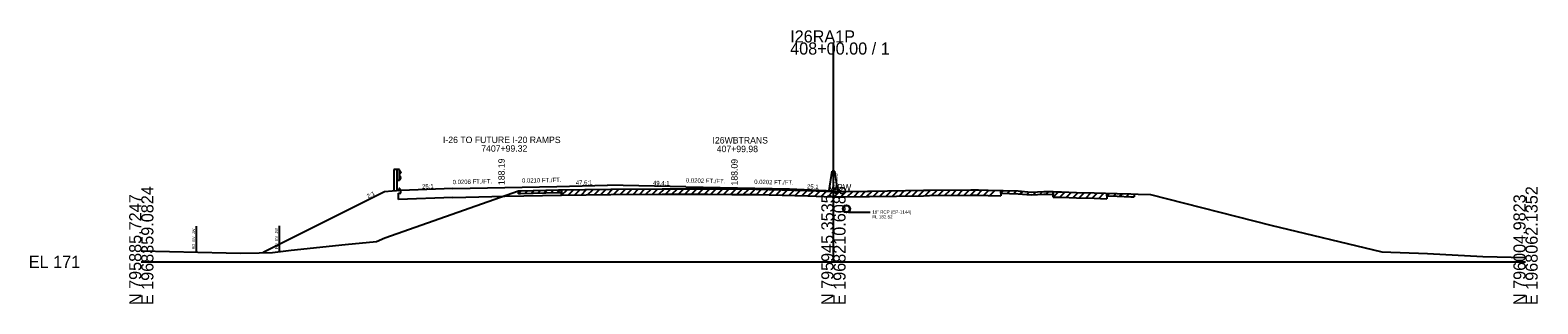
# Model space of a CAD drawing. Extents: x -44 to 4323, y -10 to 9601.
# Drawn here: x -25.7 to 322.8, y 5490.3 to 5553.5 of the extents above; entities that cross this region are included whole.
import ezdxf

# ---------------------------------------------------------------- set-up
doc = ezdxf.new("R2010")
doc.units = 0
for name, color, linetype in [('1', 7, 'Continuous'), ('DateStamp', 7, 'Continuous'), ('NotForConst', 7, 'Continuous'), ('QCQA', 7, 'Continuous'), ('RD_SHT_Bndy', 7, 'Continuous'), ('RD_SHT_Iplotshp', 7, 'Continuous'), ('RD_SHT_TX', 7, 'Continuous'), ('RD_Sketch2', 7, 'Continuous'), ('RD_XS_Base', 7, 'Continuous'), ('RD_XS_ExGround', 7, 'Continuous'), ('RD_XS_Misc_Line', 7, 'Continuous'), ('RD_XS_Pave', 7, 'Continuous'), ('RD_XS_PaveShd', 7, 'Continuous'), ('RD_XS_Pipe', 7, 'Continuous'), ('RD_XS_TX_Elev_PR', 7, 'Continuous'), ('RD_XS_TX_MatchLine', 7, 'Continuous'), ('RD_XS_TX_Profile', 7, 'Continuous'), ('RD_XS_TX_ShdSlope', 7, 'Continuous'), ('RD_XS_TX_Slope', 7, 'Continuous'), ('seal', 7, 'Continuous'), ('TR SN EXTRUDED PANEL SIGNS - GROUND MOUNTED', 7, 'Continuous')]:
    doc.layers.add(name, color=color, linetype=linetype)

msp = doc.modelspace()

# ---------------------------------------------------------------- linework, layer by layer
at = {"layer": 'DateStamp'}
msp.add_lwpolyline([(0, 5502.57), (19.61, 5502.07), (22.94, 5502.01), (27.25, 5502.11), (30.35, 5502.2), (34.65, 5502.67), (47.14, 5503.99), (54.38, 5504.74), (56.32, 5505.52), (87.16, 5516.38), (87.63, 5516.39), (96.47, 5516.63), (108.53, 5516.78), (120.44, 5516.89), (130.97, 5516.89), (136.53, 5516.84), (142.15, 5516.8), (154.06, 5516.49), (159.79, 5516.26), (162.44, 5516.24), (167.91, 5516.33), (168.35, 5516.34), (180.8, 5516.54), (182.21, 5516.56), (191.78, 5516.64), (192.21, 5516.64), (193.5, 5516.65), (195.74, 5516.59), (202.68, 5516.38), (205.73, 5516.09), (208.63, 5516.26), (209.51, 5516.24), (210.82, 5516.23), (211.42, 5516.21), (212.69, 5516.17), (216.18, 5516.05), (220.27, 5515.93), (225.56, 5515.78), (228.76, 5515.68), (230.43, 5515.65), (233.26, 5515.58), (261.12, 5508.48), (286.76, 5502.32), (297.34, 5501.9), (310.13, 5501.21), (320, 5501.04)], dxfattribs=at)
at = {"layer": 'NotForConst'}
for p, q in [((87.16, 5515.75), (87.8, 5516.4)), ((88.66, 5515.8), (89.3, 5516.44)), ((90.16, 5515.83), (90.8, 5516.48)), ((91.66, 5515.87), (92.3, 5516.52)), ((93.16, 5515.91), (93.8, 5516.56)), ((94.66, 5515.95), (95.3, 5516.6)), ((96.16, 5515.99), (96.8, 5516.63)), ((97.16, 5515.39), (98.43, 5516.65)), ((98.66, 5515.4), (99.93, 5516.67)), ((100.16, 5515.42), (101.43, 5516.69)), ((101.66, 5515.44), (102.93, 5516.71)), ((103.16, 5515.46), (104.43, 5516.73)), ((104.66, 5515.48), (105.93, 5516.75)), ((106.16, 5515.5), (107.43, 5516.77)), ((107.66, 5515.52), (108.93, 5516.79)), ((109.17, 5515.54), (110.43, 5516.8)), ((110.67, 5515.55), (111.93, 5516.81)), ((112.17, 5515.57), (113.43, 5516.83)), ((113.67, 5515.58), (114.93, 5516.84)), ((115.17, 5515.59), (116.43, 5516.86)), ((116.67, 5515.61), (117.93, 5516.87)), ((118.17, 5515.62), (119.43, 5516.88)), ((119.67, 5515.64), (120.93, 5516.89)), ((121.17, 5515.64), (122.42, 5516.89)), ((122.67, 5515.64), (123.92, 5516.89)), ((124.17, 5515.64), (125.42, 5516.89)), ((125.67, 5515.64), (126.92, 5516.89)), ((127.17, 5515.64), (128.42, 5516.89)), ((128.67, 5515.64), (129.92, 5516.89)), ((130.17, 5515.64), (131.42, 5516.88)), ((131.67, 5515.63), (132.91, 5516.87)), ((133.17, 5515.62), (134.41, 5516.86)), ((134.67, 5515.61), (135.91, 5516.85)), ((136.17, 5515.59), (137.41, 5516.83)), ((137.67, 5515.58), (138.91, 5516.82)), ((139.17, 5515.57), (140.41, 5516.81)), ((140.67, 5515.56), (141.92, 5516.8)), ((142.18, 5515.55), (143.39, 5516.76)), ((143.68, 5515.51), (144.89, 5516.72)), ((145.18, 5515.47), (146.39, 5516.69)), ((146.68, 5515.43), (147.9, 5516.65)), ((148.18, 5515.39), (149.4, 5516.61)), ((149.68, 5515.35), (150.9, 5516.57)), ((151.18, 5515.31), (152.4, 5516.53)), ((152.68, 5515.27), (153.9, 5516.49)), ((154.18, 5515.23), (155.38, 5516.43)), ((155.68, 5515.17), (156.88, 5516.37)), ((157.18, 5515.11), (158.38, 5516.31)), ((158.68, 5515.05), (159.89, 5516.26)), ((160.18, 5515), (161.42, 5516.25)), ((161.68, 5515), (162.94, 5516.25)), ((163.18, 5515), (164.45, 5516.27)), ((164.68, 5515.03), (165.95, 5516.3)), ((166.18, 5515.05), (167.45, 5516.32)), ((167.68, 5515.08), (168.95, 5516.35)), ((169.18, 5515.1), (170.45, 5516.37)), ((170.68, 5515.13), (171.96, 5516.4)), ((172.18, 5515.15), (173.46, 5516.42)), ((173.68, 5515.18), (174.96, 5516.45)), ((175.19, 5515.2), (176.46, 5516.47)), ((176.69, 5515.23), (177.96, 5516.5)), ((178.19, 5515.25), (179.46, 5516.52)), ((179.69, 5515.28), (180.96, 5516.55)), ((181.19, 5515.3), (182.45, 5516.56)), ((182.69, 5515.31), (183.95, 5516.57)), ((184.19, 5515.33), (185.45, 5516.59)), ((185.69, 5515.34), (186.95, 5516.6)), ((187.19, 5515.35), (188.45, 5516.61)), ((188.69, 5515.37), (189.95, 5516.63)), ((190.19, 5515.38), (191.45, 5516.64)), ((191.69, 5515.39), (192.94, 5516.65)), ((193.19, 5515.4), (194.42, 5516.62)), ((194.69, 5515.37), (195.91, 5516.58)), ((196.19, 5515.33), (197.41, 5516.54)), ((198.68, 5515.87), (199.28, 5516.48)), ((200.18, 5515.83), (200.78, 5516.44)), ((201.68, 5515.78), (202.28, 5516.39)), ((203.18, 5515.71), (203.75, 5516.28)), ((204.68, 5515.57), (205.25, 5516.14)), ((206.18, 5515.49), (206.84, 5516.16)), ((207.68, 5515.58), (208.34, 5516.24)), ((209.18, 5515.62), (209.8, 5516.23)), ((210.82, 5514.98), (212.04, 5516.19)), ((212.32, 5514.93), (213.53, 5516.14)), ((213.82, 5514.88), (215.03, 5516.09)), ((215.32, 5514.83), (216.54, 5516.04)), ((216.82, 5514.78), (218.04, 5515.99)), ((218.33, 5514.74), (219.54, 5515.95)), ((219.83, 5514.69), (221.04, 5515.91)), ((221.33, 5514.65), (222.54, 5515.86)), ((223.22, 5515.22), (223.83, 5515.83)), ((224.72, 5515.18), (225.33, 5515.79)), ((226.22, 5515.14), (226.82, 5515.74)), ((227.72, 5515.09), (228.32, 5515.69))]:
    msp.add_line(p, q, dxfattribs=at)
at = {"layer": 'QCQA'}
for p, q in [((97.16, 5516.64), (108.53, 5516.78)), ((97.16, 5516.64), (97.16, 5515.43)), ((108.53, 5516.78), (120.44, 5516.89)), ((120.44, 5516.89), (130.97, 5516.89)), ((130.97, 5516.89), (136.53, 5516.84)), ((136.53, 5516.84), (142.15, 5516.8)), ((142.15, 5516.8), (154.06, 5516.49)), ((154.06, 5516.49), (159.79, 5516.26)), ((159.79, 5516.26), (160, 5516.25))]:
    msp.add_line(p, q, dxfattribs=at)
at = {"layer": 'RD_SHT_Bndy'}
for p, q in [((160, 5500), (160, 5550.68)), ((0, 5500), (160, 5500)), ((160, 5500), (320, 5500))]:
    msp.add_line(p, q, dxfattribs=at)
at = {"layer": 'RD_SHT_Iplotshp'}
for p, q in [((87.16, 5515.75), (87.16, 5516.38)), ((87.16, 5515.75), (87.63, 5515.77)), ((87.63, 5515.77), (96.47, 5516)), ((96.47, 5516), (97.16, 5516.01)), ((97.16, 5515.39), (97.16, 5516.64)), ((97.16, 5516.64), (97.16, 5516.01)), ((97.16, 5515.39), (108.53, 5515.53)), ((108.53, 5515.53), (120.44, 5515.64)), ((120.44, 5515.64), (130.97, 5515.64)), ((130.97, 5515.64), (136.53, 5515.59)), ((136.53, 5515.59), (142.15, 5515.55)), ((142.15, 5515.55), (154.06, 5515.24)), ((154.06, 5515.24), (159.79, 5515.01)), ((159.79, 5515.01), (162.44, 5514.99)), ((162.44, 5514.99), (167.91, 5515.08)), ((167.91, 5515.08), (168.35, 5515.09)), ((168.35, 5515.09), (180.8, 5515.29)), ((180.8, 5515.29), (182.21, 5515.31)), ((182.21, 5515.31), (191.78, 5515.39)), ((191.78, 5515.39), (192.21, 5515.39)), ((192.21, 5515.39), (193.5, 5515.4)), ((193.5, 5515.4), (195.74, 5515.34)), ((195.74, 5515.34), (198.68, 5515.25)), ((198.68, 5516.5), (198.68, 5515.25)), ((198.68, 5515.87), (198.68, 5516.5)), ((198.68, 5515.87), (202.68, 5515.75)), ((202.68, 5515.75), (205.73, 5515.47)), ((205.73, 5515.47), (208.63, 5515.63)), ((208.63, 5515.63), (209.51, 5515.61)), ((209.51, 5515.61), (210.82, 5515.6)), ((210.82, 5514.98), (210.82, 5516.23)), ((210.82, 5516.23), (210.82, 5515.6)), ((210.82, 5514.98), (211.42, 5514.96)), ((211.42, 5514.96), (212.69, 5514.92)), ((212.69, 5514.92), (216.18, 5514.8)), ((216.18, 5514.8), (220.27, 5514.68)), ((220.27, 5514.68), (223.22, 5514.6)), ((223.22, 5515.85), (223.22, 5514.6)), ((223.22, 5515.22), (223.22, 5515.85)), ((223.22, 5515.22), (225.56, 5515.16)), ((225.56, 5515.16), (228.76, 5515.05)), ((228.76, 5515.05), (229.53, 5515.04)), ((229.53, 5515.67), (229.53, 5515.04))]:
    msp.add_line(p, q, dxfattribs=at)
at = {"layer": 'RD_Sketch2'}
for p, q in [((59.51, 5516.42), (59.57, 5516.86)), ((59.98, 5516.46), (59.51, 5516.42)), ((59.98, 5516.46), (59.73, 5516.92))]:
    msp.add_line(p, q, dxfattribs=at)
msp.add_ellipse((59.66, 5516.83), major_axis=(0, 0.131), ratio=0.686, start_param=5.388101, end_param=7.661995, dxfattribs=at)
at = {"layer": 'RD_XS_Base'}
for p, q in [((59.04, 5521.33), (58.38, 5521.33)), ((58.38, 5521.33), (58.38, 5516.27)), ((59.71, 5521.33), (59.04, 5521.33)), ((59.04, 5521.33), (59.04, 5516.39)), ((59.71, 5518.76), (59.71, 5521.33)), ((59.71, 5521.17), (59.98, 5520.73)), ((59.71, 5518.76), (59.04, 5518.76)), ((59.98, 5520.62), (59.71, 5520.18)), ((59.98, 5519.47), (59.71, 5519.91)), ((59.71, 5518.92), (59.98, 5519.36)), ((59.98, 5520.73), (59.98, 5520.62)), ((59.98, 5519.36), (59.98, 5519.47))]:
    msp.add_line(p, q, dxfattribs=at)
at = {"layer": 'RD_XS_Misc_Line'}
for p, q in [((59.48, 5515.88), (59.98, 5515.9)), ((59.48, 5514.4), (59.48, 5515.88)), ((72, 5514.9), (59.48, 5514.4)), ((59.98, 5515.9), (59.98, 5516.46)), ((72, 5514.9), (84.01, 5515.15)), ((84.01, 5515.15), (97.16, 5515.43))]:
    msp.add_line(p, q, dxfattribs=at)
at = {"layer": 'RD_XS_Pave'}
msp.add_line((57.98, 5516.3), (56.23, 5516.16), dxfattribs=at)
at = {"layer": 'RD_XS_PaveShd'}
for p, q in [((56.23, 5516.16), (28.19, 5502.14)), ((59.98, 5516.46), (57.98, 5516.3))]:
    msp.add_line(p, q, dxfattribs=at)
at = {"layer": 'RD_XS_Pipe'}
msp.add_line((163.5, 5511.52), (168.5, 5511.52), dxfattribs=at)
for radius in [0.85, 0.75]:
    msp.add_circle((163, 5512.27), radius, dxfattribs=at)
at = {"layer": 'RD_XS_TX_Elev_PR'}
for p, q in [((96.03, 5517.44), (107.81, 5517.69)), ((125.86, 5517.33), (107.81, 5517.69)), ((72, 5516.94), (59.98, 5516.46)), ((149.86, 5516.85), (160, 5516.44)), ((160, 5516.44), (160, 5516.25))]:
    msp.add_line(p, q, dxfattribs=at)
at = {"layer": 'RD_XS_TX_MatchLine'}
for p, q in [((12.67, 5508.24), (12.67, 5502.24)), ((31.84, 5508.36), (31.84, 5502.36))]:
    msp.add_line(p, q, dxfattribs=at)
at = {"layer": 'RD_XS_TX_ShdSlope'}
for p, q in [((159, 5516.46), (159.67, 5520.94)), ((160, 5520.94), (159.67, 5520.94)), ((160, 5520.93), (160.33, 5520.93)), ((161, 5516.45), (160.33, 5520.93))]:
    msp.add_line(p, q, dxfattribs=at)
at = {"layer": 'RD_XS_TX_Slope'}
for p, q in [((84.01, 5517.19), (96.03, 5517.44)), ((125.86, 5517.33), (137.86, 5517.09)), ((72, 5516.94), (84.01, 5517.19)), ((137.86, 5517.09), (149.86, 5516.85))]:
    msp.add_line(p, q, dxfattribs=at)

# ---------------------------------------------------------------- texts
at = {"layer": '1'}
for s, p in [('I-26 TO FUTURE I-20 RAMPS', (69.74, 5527.44)), ('I26WBTRANS', (132.05, 5527.34)), ('7407+99.32', (78.59, 5525.44)), ('407+99.98', (133.03, 5525.34))]:
    msp.add_text(s, height=1.5, dxfattribs=at).set_placement(p)
at = {"layer": 'RD_SHT_Bndy'}
for s, p in [('I26RA1P', (150, 5550.68)), ('408+00.00 / 1', (150, 5547.88)), ('EL 171', (-26, 5498.6))]:
    msp.add_text(s, height=2.8, dxfattribs=at).set_placement(p)
for s, p in [('E 1968359.0824', (2.8, 5490)), ('E 1968210.6088', (162.8, 5490)), ('E 1968062.1352', (322.8, 5490)), ('N 795885.7247', (0, 5490)), ('N 795945.3535', (160, 5490)), ('N 796004.9823', (320, 5490))]:
    msp.add_text(s, height=2.8, rotation=90, dxfattribs=at).set_placement(p)
at = {"layer": 'RD_SHT_TX'}
msp.add_text('187.25', height=1, rotation=90, dxfattribs=at).set_placement((161, 5516.25))
at = {"layer": 'RD_XS_ExGround'}
for s, rotation, p in [('25:1', 2.2872, (64.92, 5516.91)), ('47.6:1', 1.2042, (100.46, 5517.79)), ('49.4:1', 358.8402, (118.28, 5517.74)), ('49.4:1', 358.8401, (118.28, 5517.73)), ('25:1', 357.7096, (153.88, 5516.94))]:
    msp.add_text(s, height=1, rotation=rotation, dxfattribs=at).set_placement(p)
at = {"layer": 'RD_XS_Pipe'}
for s, p in [('18" RCP (EP-1144)', (169, 5511.14)), ('FL 182.52', (169, 5510.02))]:
    msp.add_text(s, height=0.75, dxfattribs=at).set_placement(p)
at = {"layer": 'RD_XS_TX_MatchLine'}
for p in [(12.42, 5502.89), (31.59, 5503.01)]:
    msp.add_text('RD_EV_JW', height=0.65, rotation=90, dxfattribs=at).set_placement(p)
at = {"layer": 'RD_XS_TX_Profile'}
msp.add_text('WBW', height=1.5, dxfattribs=at).set_placement((159, 5516.46))
at = {"layer": 'seal'}
for s, p in [(' 188.19', (84.01, 5517.19)), (' 188.09', (137.86, 5517.09))]:
    msp.add_text(s, height=1.5, rotation=90, dxfattribs=at).set_placement(p)
at = {"layer": 'TR SN EXTRUDED PANEL SIGNS - GROUND MOUNTED'}
for s, rotation, p in [('0.0208 FT./FT.', 1.1902, (71.98, 5517.94)), ('0.0210 FT./FT.', 1.2042, (88.01, 5518.27)), ('0.0202 FT./FT.', 358.8402, (125.88, 5518.33)), ('0.0202 FT./FT.', 358.8402, (141.68, 5518.01)), ('2:1', 26.5651, (52.42, 5514.63))]:
    msp.add_text(s, height=1, rotation=rotation, dxfattribs=at).set_placement(p)

doc.saveas('drawing.dxf')
